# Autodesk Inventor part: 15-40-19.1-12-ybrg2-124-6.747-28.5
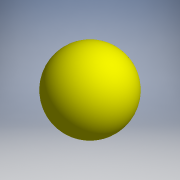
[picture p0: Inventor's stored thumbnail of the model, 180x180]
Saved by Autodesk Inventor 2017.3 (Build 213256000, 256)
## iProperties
Part Number: 15-40-19.1-12-ybrg2-124-6.747-28.5
Material: Generic
Catalog Web Link: www.cadenas.de
Description: Ball for Y units-Y-bearings
Vendor: SKF
Document SubType Name: Modeling
Designer: partserver
Manufacturer: SKF
Mass: 0.160817 g
Surface Area: 1.43012 cm^2
Volume: 0.160817 cm^3
Density: 1 g/cm^3
Appearance: PSOLRGB-255-255-0
Category: PARTsolutions
Company: SKF
Title: 15-40-19.1-12-ybrg2-124-6.747-28.5
Author: Cadenas PARTsolutions
Comments: Y-bearings
PSOL_IDENT_0: {$CADENAS_DATA\23d-libs\skf\bearings_units_and_housings\bearing_units\ball_bearing_units\y-unit_acce
PSOL_IDENT_1: ssories\ball.prj},220 {VTYP=3D},{NB=15-40-19.1-12-ybrg2-124-6.747-28.5},{LINA=15-40-19.1-12-ybrg2-12
PSOL_IDENT_2: 4-6.747-28.5},{NN=Ball for Y units},{DATE=20.08.2020 13:45:09},{GEOMDATE=29.07.2020 16:06:32},{VERSI
PSOL_IDENT_3: ON=},{LINEID=2150},{WBVAR=},{WBNUMERIC=}  {NB=15-40-19.1-12-ybrg2-124-6.747-28.5},{LINA=15-40-19.1-1
PSOL_IDENT_4: 2-ybrg2-124-6.747-28.5},{KT=DUMMY},{DD=15.0000},{D=40},{B=19.100},{C=12.000},{PITCH=28.500},{DW=6.74
PSOL_IDENT_5: 7},{FO=IEC_BBY_005},{DESIGN=ybrg2},{X=0},{PN=124}
NB: 15-40-19.1-12-ybrg2-124-6.747-28.5
NN: Ball for Y units
NT: Y-bearings
NBSYN: $DD.-$D.-$B.-$C.-$DESIGN.-$PN.-$DW.-$PITCH.
LINA: 15-40-19.1-12-ybrg2-124-6.747-28.5
CATALOG: SKF
DD: 15
D: 40
B: 19.1
C: 12
PITCH: 28.5
DW: 6.747
FO: IEC_BBY_005
DESIGN: ybrg2
SUPPLIER: SKF
ARTICLENO: 15-40-19.1-12-ybrg2-124-6.747-28.5
BOMINFO: 15-40-19.1-12-ybrg2-124-6.747-28.5
CREATOR: CADENAS GmbH
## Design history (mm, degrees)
sketch "Sketch_4"
  geometry: L1 (3.374, 14.25)-(-3.374, 14.25); L2 (3.374, 14.25)-(-3.374, 14.25); A1 r 3.374 centre (0, 14.25) between (3.374, 14.25) and (-3.374, 14.25)
  constraints: 4 end point, 2 point on circle, 1 centre point
revolve "Revolution1" sketch "Sketch_4" stored, may be unused: angle "d0" = 360 deg
node "ball_XY"
node "ball_YZ"
node "ball_ZX"
node "ball_X"
node "ball_Y"
node "ball_Z"
node "ball_Center"
body "Solid1"
